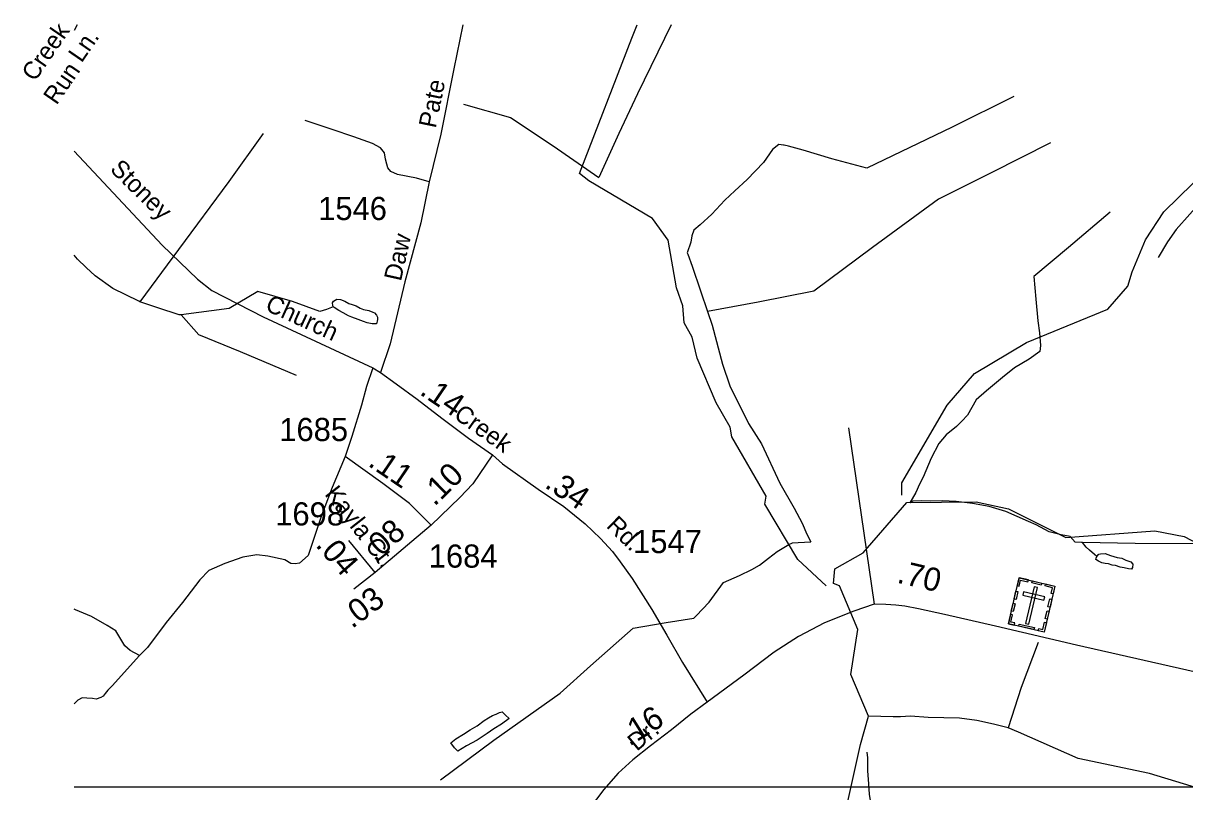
# Model space of a CAD drawing. Extents: x 2315291 to 2336543, y 597177 to 615230.
# Drawn here: x 2315470 to 2321750, y 610727 to 614879 of the extents above; entities that cross this region are included whole.
import ezdxf

# ---------------------------------------------------------------- set-up
doc = ezdxf.new("R2010")
doc.units = 0
for name, color, linetype in [('Exist Cultural Cemetery CELL', 7, 'Continuous'), ('Exist Hydrographic Creek Single Shore', 7, 'Continuous'), ('Exist Hydrographic Misc Water Feature', 7, 'Continuous'), ('Exist Road Non-System Type 51', 7, 'Continuous'), ('Exist Road Non-System Type 51 Label', 7, 'Continuous'), ('Exist Road Secondary Mileage Hundredths English Label', 7, 'Continuous'), ('Exist Road Secondary Type 51 Attributed', 7, 'Continuous'), ('Exist Road Secondary Type 51 Label', 7, 'Continuous'), ('Exist Road Secondary Type 51 Number Label', 7, 'Continuous'), ('Map Preparation Inset Cut Line', 7, 'Continuous')]:
    doc.layers.add(name, color=color, linetype=linetype)

msp = doc.modelspace()

# ---------------------------------------------------------------- linework, layer by layer
at = {"layer": 'Exist Cultural Cemetery CELL'}
for points in [[(2320853.9, 611883), (2321047.8, 611837.8), (2320989.9, 611589.8), (2320796, 611635.1)], [(2320844, 611840.8), (2320855.1, 611838.3), (2320862.4, 611869.6), (2320901.9, 611860.4), (2320904.4, 611871.2), (2320853.9, 611883)], [(2320827.2, 611768.6), (2320837, 611810.8), (2320848.1, 611808.2), (2320838.3, 611766)], [(2320878.2, 611807.5), (2320873.9, 611789.3), (2320988.6, 611762.5), (2320992.8, 611780.7)], [(2320953.4, 611829.7), (2320935.2, 611834), (2320889.1, 611636.5), (2320907.3, 611632.2)], [(2320926, 611866.2), (2320976.5, 611854.4), (2320973.9, 611843.3), (2320923.4, 611855.1)], [(2321038, 611795.5), (2321026.9, 611798.1), (2321034.2, 611829.5), (2320994.7, 611838.7), (2320997.3, 611849.5), (2321047.8, 611837.7)], [(2320811.9, 611703.2), (2320821.7, 611745.4), (2320832.8, 611742.8), (2320823, 611700.6)], [(2321010.3, 611727), (2321020.1, 611769.1), (2321031.2, 611766.6), (2321021.3, 611724.4)], [(2320828.2, 611627.6), (2320830.9, 611638.8), (2320809.4, 611643.8), (2320818.6, 611683.1), (2320807.8, 611685.7), (2320796, 611635.1)], [(2320995.2, 611662.8), (2321005.1, 611704.9), (2321016.2, 611702.4), (2321006.3, 611660.2)], [(2320854.6, 611633.2), (2320937.2, 611613.9), (2320934.6, 611602.8), (2320852, 611622.1)], [(2320957.6, 611597.3), (2320960.2, 611608.5), (2320981.7, 611603.5), (2320990.9, 611642.9), (2321001.7, 611640.4), (2320989.9, 611589.8)]]:
    msp.add_lwpolyline(points, close=True, dxfattribs=at)
at = {"layer": 'Exist Hydrographic Creek Single Shore'}
for points in [[(2320247.9, 612290.3), (2320621.2, 612293.7), (2320796.3, 612254.9), (2321106.3, 612100.1), (2321588.2, 612136), (2321747.3, 612106.4), (2322358.2, 611786.5), (2322475.3, 611755.1), (2322750.2, 611815.5), (2322891.3, 611867.1), (2322965.3, 611968.6), (2323061.3, 612310.4), (2323288.3, 612903.8), (2323417.3, 613306.1), (2323466.3, 613396.6), (2323597.3, 613533.3), (2323811.4, 613778.1)], [(2319883.7, 611839.2), (2319851.2, 611852.4), (2319858.1, 611931.8), (2320011.7, 612018.5), (2320247.9, 612290.3)], [(2319979.2, 610046.1), (2319994.3, 610155), (2319975.3, 610321.6), (2319950.2, 610369.8), (2319906.2, 610578.1), (2319995.9, 610982.4), (2320039.3, 611136.1), (2319944.8, 611360.6), (2319982.2, 611602.9), (2319883.7, 611839.2)]]:
    msp.add_lwpolyline(points, dxfattribs=at)
at = {"layer": 'Exist Hydrographic Misc Water Feature'}
for points in [[(2319810.9, 611839.2), (2319658.3, 611982.4), (2319480.3, 612280.4), (2319487.2, 612323.4), (2319301.3, 612644), (2319292.2, 612696.1), (2319216.2, 612827.6), (2319113.2, 613069.5), (2319087.2, 613183.4), (2319044.1, 613260.4), (2319035.3, 613351.9), (2319001.3, 613448.9), (2318956.2, 613706.4), (2318872.3, 613824.4), (2318528.2, 614027.1), (2318478.2, 614067.7), (2318761.2, 614797.9), (2318789.9, 614870.5)], [(2318972.8, 614870.5), (2318791.3, 614497.2), (2318689.2, 614282.2), (2318581.7, 614045)], [(2320220.3, 612330.1), (2320220.3, 612395.7), (2320465.3, 612815.8), (2320613.2, 612985.9), (2320894.3, 613154.7), (2321334.4, 613333.4), (2321441.2, 613459.1), (2321465.2, 613535.6), (2321538.2, 613709.2), (2321637.2, 613860.8), (2321950.3, 614165.6), (2321998.3, 614315.2), (2321992.2, 614866.3)], [(2322089.4, 614870.5), (2322102.5, 614580.8), (2322115.8, 614301), (2322050.8, 614214.3), (2321987.2, 614131.8), (2321898.7, 614004.8), (2321851.3, 613930.4), (2321703.6, 613764.9), (2321656.3, 613698.2), (2321605.4, 613613.8)], [(2320826.4, 614482.9), (2320492, 614317.5), (2320030.6, 614096.5), (2319842.2, 614146.4), (2319685.9, 614192.7), (2319607.8, 614214.1), (2319583.6, 614219.8), (2319579.9, 614219.6), (2319555.9, 614223.6), (2319520, 614197), (2319472.5, 614126.6), (2319383.7, 614033.7), (2319316.4, 613972.9), (2319263.1, 613922.6), (2319192, 613847.7), (2319130.5, 613789.2), (2319095.2, 613760.9), (2319084.9, 613730.8), (2319079.4, 613696.7), (2319060.3, 613638.4)], [(2317849.9, 614441), (2318105, 614369.8), (2318334.4, 614216.4), (2318581.7, 614045)], [(2316766.4, 614283.3), (2316581.7, 614023.6), (2316309.3, 613656.7), (2316100.6, 613373)], [(2321024.5, 614233.3), (2320702.8, 614070), (2320418.4, 613928.7), (2320061.2, 613667), (2319744.2, 613432), (2319442.7, 613372.8), (2319169.4, 613321.8)], [(2321346.4, 613858.8), (2321120.7, 613666.5), (2320934.5, 613510.8), (2320943.9, 613388.9), (2320955.4, 613270.8), (2320963.8, 613207.1), (2320970.6, 613137.2), (2320966.9, 613105.2)], [(2319060.3, 613638.4), (2319062.4, 613630.4), (2319087, 613566.6), (2319132.3, 613433.2), (2319169.4, 613321.8)], [(2316100.6, 613373), (2316094.9, 613376.7), (2315954, 613445.3), (2315859.3, 613513.9), (2315810.7, 613559.3), (2315762.7, 613605.1), (2315744.5, 613625.1)], [(2317146.4, 613346.1), (2317110.3, 613331.6), (2317073, 613321.1), (2316925.9, 613375.6), (2316737.7, 613429.5), (2316582.7, 613338.1), (2316323.1, 613303.3)], [(2317146.4, 613346.1), (2317144.1, 613353.7), (2317142.3, 613367.8), (2317148.2, 613377.9), (2317166.1, 613388.2), (2317186.1, 613386.3), (2317207.9, 613376.6), (2317230.2, 613364.7), (2317248.3, 613359.2), (2317270.4, 613351.4), (2317292.2, 613339.5), (2317310.4, 613331.5), (2317338.5, 613326.1), (2317360.6, 613318.3), (2317368.8, 613314.3), (2317380.7, 613302.3), (2317384.8, 613290.3), (2317385, 613278.6), (2317383, 613268.7), (2317379.3, 613254.7), (2317357.2, 613254.4), (2317329.3, 613260.2), (2317309.2, 613267.7), (2317281.1, 613277.6), (2317246.8, 613291.3), (2317228.6, 613298.9), (2317198.9, 613314.7), (2317176.5, 613326.2), (2317150.3, 613342.3), (2317146.4, 613346.1)], [(2316323.1, 613303.3), (2316313.4, 613303.2), (2316197, 613341.8), (2316100.6, 613373)], [(2319169.4, 613321.8), (2319194.2, 613247.9), (2319250.4, 613036.7), (2319290, 612919.2), (2319391.9, 612716.5), (2319461.2, 612607.1), (2319561.3, 612394.6), (2319638.8, 612259.3), (2319681.2, 612177.8), (2319706.2, 612118.1), (2319729, 612076.6)], [(2316946.6, 612975.9), (2316645, 613102.8), (2316418.4, 613196.2), (2316323.1, 613303.3)], [(2320966.9, 613105.2), (2320909.5, 613064.4), (2320829.9, 613017.6), (2320764.7, 612965), (2320677.8, 612892.1), (2320622, 612843.7), (2320574.8, 612761.1), (2320545.1, 612728.7), (2320515.4, 612700.8), (2320460, 612655.9), (2320420.4, 612607.6), (2320379.2, 612529), (2320334.7, 612426.6), (2320315.2, 612388.6), (2320295.6, 612344.5), (2320264, 612288)], [(2321196.1, 612074.3), (2321191.8, 612074.2), (2321158.2, 612076), (2321129.5, 612105.4), (2321081.3, 612115.1), (2321017.5, 612130.4), (2320947.2, 612169.4), (2320904.8, 612187.1), (2320781.9, 612241.7), (2320691.7, 612268.7), (2320602.1, 612283.8), (2320513.7, 612294.6), (2320438.3, 612297.9), (2320373.9, 612297.4), (2320325.7, 612298.6), (2320279.8, 612296.2), (2320264, 612288)], [(2317725.4, 610791.6), (2318015, 611006.4), (2318372.2, 611260.4), (2318536.6, 611408.1), (2318768.3, 611610.4), (2318945.7, 611642.1), (2319095.4, 611665.8), (2319107.3, 611677.8), (2319178.4, 611750.6), (2319255.3, 611857.5), (2319342.9, 611896.2), (2319408.3, 611926.9), (2319450.1, 611951.4), (2319499.7, 611988.2), (2319545.3, 612024.3), (2319583, 612047), (2319609, 612063), (2319628.7, 612071.4), (2319658.9, 612073.7), (2319729, 612076.6)], [(2321274.7, 611997.2), (2321262.6, 612008.8), (2321234.3, 612032.5), (2321216, 612048.6), (2321196.1, 612074.3)], [(2321994.4, 611988.7), (2321837.5, 612067), (2321481.8, 612069), (2321196.1, 612074.3)], [(2321274.7, 611997.2), (2321284.7, 612011.1), (2321294.4, 612013.3), (2321320.4, 612013.5), (2321348.5, 612003.9), (2321384.8, 611992.4), (2321408.8, 611988.4), (2321430.5, 611978.6), (2321446.7, 611973), (2321459.2, 611969), (2321469.1, 611957), (2321467.4, 611939), (2321461.5, 611928.9), (2321445.1, 611931), (2321423.1, 611936.7), (2321401.2, 611940.4), (2321375.2, 611950.1), (2321357.3, 611952), (2321337, 611957.8), (2321319, 611959.7), (2321300.9, 611963.2), (2321283.1, 611973.2), (2321268.5, 611981.1), (2321270.8, 611988.9), (2321274.7, 611997.2)], [(2320956.6, 611533.9), (2320866, 611289.7), (2320795.2, 611073)], [(2317961.9, 611111.7), (2317985.6, 611126), (2318007.6, 611138.5), (2318027.7, 611146.4), (2318045.5, 611154.7), (2318059.5, 611159.1), (2318077.3, 611141.4), (2318097.8, 611123.3), (2318056.2, 611093), (2318014.4, 611066.5), (2317978.9, 611042.2), (2317923.5, 611005.6), (2317867.3, 610975.1), (2317843.7, 610960.8), (2317819.8, 610946.6), (2317801.9, 610964.3), (2317781.4, 610992.1), (2317809.3, 611012.2), (2317850.7, 611038.8), (2317886.4, 611061.1), (2317924.1, 611083.4), (2317961.9, 611111.7)], [(2320795.2, 611073), (2320716.4, 611092.7), (2320625.9, 611112.4), (2320531.4, 611124.2), (2320362.1, 611128.2), (2320267.6, 611136.1), (2320212.5, 611132.1), (2320172.7, 611131.7), (2320039.3, 611136.1)], [(2322445.3, 610582.5), (2322068.4, 610670.5), (2321558.9, 610824.9), (2321173.1, 610907.6), (2320850.3, 611049.4), (2320795.2, 611073)], [(2320031.5, 610941.8), (2320034.7, 610910.4), (2320033.7, 610840.4), (2320040.5, 610770.5), (2320043.3, 610714.5), (2320051.5, 610668.6), (2320050.5, 610598.7), (2320057.1, 610536.8), (2320067.5, 610487), (2320080, 610438.9), (2320088.5, 610405.1), (2320102.8, 610351.5), (2320111.2, 610307.6), (2320121.9, 610259.4), (2320130.5, 610223.7), (2320136.8, 610197.9), (2320143, 610165.8), (2320141.6, 610119.8), (2320142, 610073.9), (2320138.7, 610027.7), (2320134.6, 609995.9), (2320128.4, 609990)]]:
    msp.add_lwpolyline(points, dxfattribs=at)
at = {"layer": 'Exist Road Non-System Type 51'}
msp.add_line((2319931.6, 612693.3), (2320070.4, 611739.8), dxfattribs=at)
for points in [[(2315761.7, 614870.5), (2315744.5, 614838.7)], [(2317665.4, 614022.2), (2317597, 614042), (2317493.3, 614061.9), (2317458, 614077.4), (2317440.3, 614097.3), (2317435.9, 614117.1), (2317429.3, 614143.6), (2317422.7, 614179), (2317400.6, 614205.5), (2317358.6, 614229.8), (2317257.1, 614265.1), (2317140.1, 614304.9), (2316994.5, 614353.4)], [(2317359.9, 613017.9), (2317326.4, 612915.9), (2317298, 612815.8), (2317246.4, 612645.6), (2317211.3, 612538.9)], [(2317211.3, 612538.9), (2317139.7, 612370.4), (2317081.3, 612213.6), (2317010.5, 612004.2), (2316964.1, 611961.9), (2316939.9, 611957.9), (2316915.8, 611959.9), (2316883.5, 611980.1), (2316792.9, 612000.2), (2316732.4, 612006.3), (2316657.9, 611994.2), (2316559.1, 611959.9), (2316472.5, 611921.6), (2316424.1, 611871.2), (2316331.4, 611750.3), (2316242.8, 611641.4), (2316142.6, 611506), (2316099.1, 611463.7)], [(2316099.1, 611463.7), (2316048.7, 611491), (2316018.6, 611514.6), (2315992.1, 611560.4), (2315969.7, 611596.1), (2315923.5, 611625.6), (2315838.9, 611674.8), (2315752.6, 611709.7), (2315744.5, 611713.5)], [(2316099.1, 611463.7), (2315950.9, 611300), (2315927.2, 611275.9), (2315913.4, 611257.7), (2315901.5, 611243.6), (2315889.6, 611235.5), (2315863.8, 611227.3), (2315843.6, 611231.1), (2315813.7, 611232.7), (2315787.7, 611234.4), (2315765.8, 611222.1), (2315744.5, 611201.8)]]:
    msp.add_lwpolyline(points, dxfattribs=at)
at = {"layer": 'Exist Road Secondary Type 51 Attributed'}
msp.add_line((2317373.1, 611910.8), (2317229.8, 612083.8), dxfattribs=at)
for points in [[(2317846.3, 614870.5), (2317797.9, 614632.8), (2317727.2, 614279.5), (2317665.4, 614022.2), (2317619.1, 613801.3), (2317533, 613482.2), (2317453.5, 613147.6), (2317401.4, 612992)], [(2315744.5, 614187.1), (2316221, 613679.8), (2316411.8, 613496.6), (2316489.1, 613434.7), (2316767.2, 613292.3), (2317359.9, 613017.9), (2317401.4, 612992)], [(2317401.4, 612992), (2317486.6, 612930.4), (2317599.2, 612848.1), (2317732.4, 612744.5), (2317876.5, 612636.5), (2318006.6, 612546.4)], [(2317674.8, 612167.7), (2317558.7, 612284.3), (2317413.8, 612392.9), (2317211.3, 612538.9)], [(2318006.6, 612546.4), (2317899.9, 612391.2), (2317829.8, 612316.2), (2317674.8, 612167.7)], [(2318006.6, 612546.4), (2318060.9, 612498.1), (2318254.2, 612362.3), (2318393.3, 612267.9), (2318508.4, 612175.2), (2318591.7, 612095.1), (2318656.7, 612025.1), (2318696.7, 611970), (2318761.8, 611878.3), (2318868.5, 611711.5), (2318950.1, 611573), (2319033.5, 611426.2), (2319168.5, 611211)], [(2317674.8, 612167.7), (2317373.1, 611910.8)], [(2317373.1, 611910.8), (2317256.4, 611820.7)], [(2322661.1, 611328.6), (2322627.8, 611313.6), (2322537.8, 611286.9), (2322446.1, 611270.2), (2322351, 611263.6), (2322227.7, 611278.6), (2321760.9, 611383.7), (2321164.1, 611518.8), (2320727.3, 611621.4), (2320450.5, 611684.8), (2320310.5, 611714.8), (2320235.5, 611729.8), (2320187.1, 611734.8), (2320133.8, 611738.2), (2320070.4, 611739.8), (2319960.4, 611703.1), (2319802, 611639.7), (2319662, 611566.3), (2319530.3, 611481.3), (2319365.3, 611356.2), (2319168.5, 611211)], [(2319168.5, 611211), (2319078.5, 611146), (2318975.1, 611060.9), (2318861.8, 610975.8), (2318765.2, 610899.6), (2318687, 610827), (2318621.3, 610753.3), (2318608.7, 610739.2), (2318568.7, 610686.7), (2318530.5, 610637)]]:
    msp.add_lwpolyline(points, dxfattribs=at)
at = {"layer": 'Map Preparation Inset Cut Line'}
for p, q in [((2315744.5, 610753.3), (2318621.3, 610753.3)), ((2318621.3, 610753.3), (2322567.3, 610753.3))]:
    msp.add_line(p, q, dxfattribs=at)

# ---------------------------------------------------------------- texts
at = {"layer": 'Exist Road Non-System Type 51 Label'}
for s, p in [('Creek', (2315532.8, 614559.1)), ('Ln.', (2315785.1, 614661)), ('Run', (2315650.1, 614432.9))]:
    msp.add_text(s, height=95, rotation=55.47314, dxfattribs=at).set_placement(p)
at = {"layer": 'Exist Road Secondary Mileage Hundredths English Label'}
for s, rotation, p in [('.14', 325.83759, (2317607.9, 612877.4)), ('.11', 325.83759, (2317328.8, 612491.2)), ('.10', 44.53201, (2317693.7, 612265.1)), ('.34', 325.83759, (2318283.4, 612374.8)), ('.08', 41.52029, (2317370.6, 611963.5)), ('.04', 311.08846, (2317046.5, 612057.1)), ('.70', 346.78196, (2320189.1, 611857.5)), ('.03', 37.01979, (2317247.6, 611605.2)), ('.16', 32.05856, (2318747.3, 610970.2))]:
    msp.add_text(s, height=125, rotation=rotation, dxfattribs=at).set_placement(p)
at = {"layer": 'Exist Road Secondary Type 51 Label'}
for s, rotation, p in [('Pate', 78.49806, (2317699.9, 614308)), ('Stoney', 315.59795, (2315934.2, 614084.8)), ('Daw', 77.33752, (2317511.9, 613481.2)), ('Church', 335.45923, (2316772.5, 613330.2)), ('Creek', 324.59385, (2317791.8, 612749.7)), ('Kayla Ct.', 308.10324, (2317095.8, 612333.7)), ('Rd.', 315.63349, (2318617.4, 612158.8)), ('Dr.', 39.84315, (2318787.2, 610942.7))]:
    msp.add_text(s, height=95, rotation=rotation, dxfattribs=at).set_placement(p)
at = {"layer": 'Exist Road Secondary Type 51 Number Label'}
for s, p in [('1546', (2317064.4, 613815.6)), ('1685', (2316854.2, 612621.6)), ('1698', (2316832.3, 612165.8)), ('1547', (2318767.1, 612016.3)), ('1684', (2317662.4, 611937.9))]:
    msp.add_text(s, height=125, dxfattribs=at).set_placement(p)

doc.saveas('drawing.dxf')
